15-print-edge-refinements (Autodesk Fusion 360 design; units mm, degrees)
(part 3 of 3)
extrude "Extrude2" cut sketch "E Rear Bearing Cap Bolt seed" profile of C1 along normal blind 3 (= "capThickness")
circular_pattern "C-Pattern1" TotalAngle 360
chamfer "Chamfer1" distance 0.3 (= "bedRelief")
work_plane "WorkPlane1" AlongDistance -29 (= "hubFace - adapterThickness") ExtraOffset 0
sketch "F Adapter Flange sketch" plane through (-20.5061, -20.5061, 0) normal (0.7071, 0.7071, 0) x axis (0, 0, 1)
  circle C1 centre (0, 0) radius 38
  dimension "d967" diameter C1 = 76 (= "mountOD")
extrude "Extrude1" new body sketch "F Adapter Flange sketch" along normal blind 6 (= "adapterThickness")
work_plane "WorkPlane2" AlongDistance -23 (= "hubFace") ExtraOffset 0
sketch "F Centering Pilot sketch" plane through (-16.2635, -16.2635, 0) normal (0.7071, 0.7071, 0) x axis (0, 0, 1)
  circle C1 centre (0, 0) radius 25
  circle C2 centre (0, 0) radius 17
  dimension "d972" diameter C1 = 50 (= "pilotDiameter")
  dimension "d973" diameter C2 = 34 (= "pilotInside")
extrude "Extrude2" add sketch "F Centering Pilot sketch" along normal blind 2 (= "pilotHeight")
work_plane "WorkPlane3" AlongDistance -29 (= "hubFace - adapterThickness") ExtraOffset 0
sketch "F Shaft Clearance sketch" plane through (-20.5061, -20.5061, 0) normal (0.7071, 0.7071, 0) x axis (0, 0, 1)
  circle C1 centre (0, 0) radius 4.25
  dimension "d978" diameter C1 = 8.5 (= "shaftClearance")
extrude "Extrude3" cut sketch "F Shaft Clearance sketch" along normal blind 6 (= "adapterThickness")
work_plane "WorkPlane4" AlongDistance -29 (= "hubFace - adapterThickness") ExtraOffset 0
sketch "F Mount Holes" plane through (-20.5061, -20.5061, 0) normal (0.7071, 0.7071, 0) x axis (0, 0, 1)
  circle C1 centre (22.6274, 22.6274) radius 2.15
  circle C2 centre (-22.6274, 22.6274) radius 2.15
  circle C3 centre (-22.6274, -22.6274) radius 2.15
  circle C4 centre (22.6274, -22.6274) radius 2.15
  point P1 (0, 0)
  point P2 (22.6274, 22.6274)
  point P3 (-22.6274, 22.6274)
  point P4 (-22.6274, -22.6274)
  point P5 (22.6274, -22.6274)
  dimension "d983" distance P1 P2 = 22.6274 (= "abs(mountCircle / ( 2 * sqrt(2) ))")
  dimension "d984" distance P1 P2 = 22.6274 (= "abs(mountCircle / ( 2 * sqrt(2) ))")
  dimension "d985" diameter C1 = 4.3 (= "m4Clearance")
  dimension "d986" distance P1 P3 = 22.6274 (= "abs(-mountCircle / ( 2 * sqrt(2) ))")
  dimension "d987" distance P1 P3 = 22.6274 (= "abs(mountCircle / ( 2 * sqrt(2) ))")
  dimension "d988" diameter C2 = 4.3 (= "m4Clearance")
  dimension "d989" distance P1 P4 = 22.6274 (= "abs(-mountCircle / ( 2 * sqrt(2) ))")
  dimension "d990" distance P1 P4 = 22.6274 (= "abs(-mountCircle / ( 2 * sqrt(2) ))")
  dimension "d991" diameter C3 = 4.3 (= "m4Clearance")
  dimension "d992" distance P1 P5 = 22.6274 (= "abs(mountCircle / ( 2 * sqrt(2) ))")
  dimension "d993" distance P1 P5 = 22.6274 (= "abs(-mountCircle / ( 2 * sqrt(2) ))")
  dimension "d994" diameter C4 = 4.3 (= "m4Clearance")
extrude "Extrude4" cut sketch "F Mount Holes" along normal blind 6 (= "adapterThickness")
sketch "F Compression Sleeve Holes" plane through (-20.5061, -20.5061, 0) normal (0.7071, 0.7071, 0) x axis (0, 0, 1)
  line L1 (11.3137, 0) -> (0, 0)
  line L2 (0, 11.3137) -> (0, 0)
  line L3 (-11.3137, 0) -> (0, 0)
  line L4 (0, -11.3137) -> (0, 0)
  circle C1 centre (11.3137, 0) radius 4.1
  circle C2 centre (0, 11.3137) radius 4.1
  circle C3 centre (-11.3137, 0) radius 4.1
  circle C4 centre (0, -11.3137) radius 4.1
  point P1 (0, 0)
  point P2 (11.3137, 0)
  point P3 (0, 11.3137)
  point P5 (0, -11.3137)
  horizontal L1
  vertical L2
  horizontal L3
  vertical L4
  dimension "d997" distance P1 P2 = 11.3137 (= "abs(hubHoleSpacing / sqrt(2))")
  dimension "d998" diameter C1 = 8.2 (= "sleeveOD + sleeveAllowance")
  dimension "d999" distance P1 P3 = 11.3137 (= "abs(hubHoleSpacing / sqrt(2))")
  dimension "d1000" diameter C2 = 8.2 (= "sleeveOD + sleeveAllowance")
  dimension "d59" = 150 (= "bodyWidth")
  dimension "d1002" diameter C3 = 8.2 (= "sleeveOD + sleeveAllowance")
  dimension "d1003" distance P1 P5 = 11.3137 (= "abs(-hubHoleSpacing / sqrt(2))")
  dimension "d1004" diameter C4 = 8.2 (= "sleeveOD + sleeveAllowance")
  dimension "d1001" distance = 11.3137 (= "abs(-hubHoleSpacing / sqrt(2))")
extrude "Extrude5" cut sketch "F Compression Sleeve Holes" profile of C1 C2 C3 C4 along normal blind 6 (= "adapterThickness")
chamfer "Chamfer1" distance 0.4 (= "entryChamfer")
chamfer "Chamfer2" distance 0.3 (= "bedRelief")
work_plane "WorkPlane1" AlongDistance 0.5 (= "qFront") ExtraOffset 0
sketch "Front 608 sketch" plane through (0.3536, 0.3536, 0) normal (0.7071, 0.7071, 0) x axis (0, 0, 1)
  circle C1 centre (0, 0) radius 11
  circle C2 centre (0, 0) radius 4
  dimension "d1011" diameter C1 = 22 (= "bearingOD")
  dimension "d1012" diameter C2 = 8 (= "bearingID")
extrude "Extrude1" new body sketch "Front 608 sketch" along normal blind 7 (= "bearingWidth")
work_plane "WorkPlane2" AlongDistance 25.6 (= "qRearBearing") ExtraOffset 0
sketch "Rear 608 sketch" plane through (18.1019, 18.1019, 0) normal (0.7071, 0.7071, 0) x axis (0, 0, 1)
  circle C1 centre (0, 0) radius 11
  circle C2 centre (0, 0) radius 4
  dimension "d1017" diameter C1 = 22 (= "bearingOD")
  dimension "d1018" diameter C2 = 8 (= "bearingID")
extrude "Extrude2" new body sketch "Rear 608 sketch" along normal blind 7 (= "bearingWidth")
work_plane "WorkPlane1" AlongDistance -24 ExtraOffset 0
sketch "Metal Shaft sketch" plane through (-16.9706, -16.9706, 0) normal (0.7071, 0.7071, 0) x axis (0, 0, 1)
  circle C1 centre (0, 0) radius 4
  dimension "d1023" diameter C1 = 8
extrude "Extrude1" new body sketch "Metal Shaft sketch" along normal blind 60
work_plane "WorkPlane1" AlongDistance -3.5 (= "qFront - 4 mm") ExtraOffset 0
sketch "Front Inner Ring Spacer sketch" plane through (-2.4749, -2.4749, 0) normal (0.7071, 0.7071, 0) x axis (0, 0, 1)
  circle C1 centre (0, 0) radius 5
  circle C2 centre (0, 0) radius 4
  dimension "d1028" diameter C1 = 10
  dimension "d1029" diameter C2 = 8
extrude "Extrude1" new body sketch "Front Inner Ring Spacer sketch" along normal blind 4
work_plane "WorkPlane2" AlongDistance 7.5 (= "qFront + bearingWidth") ExtraOffset 0
sketch "Rear Inner Ring Spacer sketch" plane through (5.3033, 5.3033, 0) normal (0.7071, 0.7071, 0) x axis (0, 0, 1)
  circle C1 centre (0, 0) radius 5
  circle C2 centre (0, 0) radius 4
  dimension "d1034" diameter C1 = 10
  dimension "d1035" diameter C2 = 8
extrude "Extrude2" new body sketch "Rear Inner Ring Spacer sketch" along normal blind 4
work_plane "WorkPlane1" AlongDistance -12.5 (= "qFront - 13 mm") ExtraOffset 0
sketch "Front Collar Maximum Envelope sketch" plane through (-8.8388, -8.8388, 0) normal (0.7071, 0.7071, 0) x axis (0, 0, 1)
  circle C1 centre (0, 0) radius 11.2
  circle C2 centre (0, 0) radius 4
  dimension "d1040" diameter C1 = 22.4
  dimension "d1041" diameter C2 = 8
extrude "Extrude1" new body sketch "Front Collar Maximum Envelope sketch" along normal blind 9
work_plane "WorkPlane2" AlongDistance 11.5 (= "qFront + bearingWidth + 4 mm") ExtraOffset 0
sketch "Rear Collar Maximum Envelope sketch" plane through (8.1317, 8.1317, 0) normal (0.7071, 0.7071, 0) x axis (0, 0, 1)
  circle C1 centre (0, 0) radius 11.2
  circle C2 centre (0, 0) radius 4
  dimension "d1046" diameter C1 = 22.4
  dimension "d1047" diameter C2 = 8
extrude "Extrude2" new body sketch "Rear Collar Maximum Envelope sketch" along normal blind 9
work_plane "WorkPlane1" AlongDistance 0 ExtraOffset 0
sketch "Spacer Pattern Axis" plane through (0, 0, 0) normal (0.7071, 0.7071, 0) x axis (0, 0, 1)
  circle C1 centre (0, 0) radius 0.5
  dimension "d1052" diameter C1 = 1
work_plane "WorkPlane2" AlongDistance 10.6 (= "qFrontBack") ExtraOffset 0
sketch "Support Spacer OD" plane through (7.4953, 7.4953, 0) normal (0.7071, 0.7071, 0) x axis (0, 0, 1)
  line L1 (17, 0) -> (0, 0)
  circle C1 centre (17, 0) radius 3
  circle C2 centre (17, 0) radius 1.6
  point P1 (0, 0)
  point P2 (17, 0)
  horizontal L1
  dimension "d1055" distance P1 P2 = 17 (= "supportCircle / 2")
  dimension "d1056" diameter C1 = 6 (= "supportSpacerOD")
  dimension "d1057" diameter C2 = 3.2
extrude "Extrude1" new body sketch "Support Spacer OD" profile of C1 C2 along normal blind 12 (= "supportSpacer")
circular_pattern "C-Pattern1" TotalAngle 360
work_plane "WorkPlane1" AlongDistance -29 (= "hubFace - adapterThickness") ExtraOffset 0
sketch "Sleeve 1 Outer" plane through (-20.5061, -20.5061, 0) normal (0.7071, 0.7071, 0) x axis (0, 0, 1)
  line L1 (11.3137, 0) -> (0, 0)
  circle C1 centre (11.3137, 0) radius 4
  circle C2 centre (11.3137, 0) radius 2.15
  point P1 (0, 0)
  point P2 (11.3137, 0)
  horizontal L1
  dimension "d1064" distance P1 P2 = 11.3137 (= "abs(hubHoleSpacing / sqrt(2))")
  dimension "d1065" diameter C1 = 8 (= "sleeveOD")
  dimension "d1066" diameter C2 = 4.3
extrude "Extrude1" new body sketch "Sleeve 1 Outer" profile of C1 C2 along normal blind 6 (= "adapterThickness")
work_plane "WorkPlane2" AlongDistance -29 (= "hubFace - adapterThickness") ExtraOffset 0
sketch "Sleeve 2 Outer" plane through (-20.5061, -20.5061, 0) normal (0.7071, 0.7071, 0) x axis (0, 0, 1)
  line L1 (0, 11.3137) -> (0, 0)
  circle C1 centre (0, 11.3137) radius 4
  circle C2 centre (0, 11.3137) radius 2.15
  point P1 (0, 0)
  point P2 (0, 11.3137)
  vertical L1
  dimension "d1071" distance P1 P2 = 11.3137 (= "abs(hubHoleSpacing / sqrt(2))")
  dimension "d1072" diameter C1 = 8 (= "sleeveOD")
  dimension "d1073" diameter C2 = 4.3
extrude "Extrude2" new body sketch "Sleeve 2 Outer" profile of C1 C2 along normal blind 6 (= "adapterThickness")
work_plane "WorkPlane3" AlongDistance -29 (= "hubFace - adapterThickness") ExtraOffset 0
sketch "Sleeve 3 Outer" plane through (-20.5061, -20.5061, 0) normal (0.7071, 0.7071, 0) x axis (0, 0, 1)
  line L1 (-11.3137, 0) -> (0, 0)
  circle C1 centre (-11.3137, 0) radius 4
  circle C2 centre (-11.3137, 0) radius 2.15
  point P1 (0, 0)
  point P2 (-11.3137, 0)
  horizontal L1
  dimension "d1078" distance P1 P2 = 11.3137 (= "abs(-hubHoleSpacing / sqrt(2))")
  dimension "d1079" diameter C1 = 8 (= "sleeveOD")
  dimension "d1080" diameter C2 = 4.3
extrude "Extrude3" new body sketch "Sleeve 3 Outer" profile of C1 C2 along normal blind 6 (= "adapterThickness")
work_plane "WorkPlane4" AlongDistance -29 (= "hubFace - adapterThickness") ExtraOffset 0
sketch "Sleeve 4 Outer" plane through (-20.5061, -20.5061, 0) normal (0.7071, 0.7071, 0) x axis (0, 0, 1)
  line L1 (0, -11.3137) -> (0, 0)
  circle C1 centre (0, -11.3137) radius 4
  circle C2 centre (0, -11.3137) radius 2.15
  point P1 (0, 0)
  point P2 (0, -11.3137)
  vertical L1
  dimension "d1085" distance P1 P2 = 11.3137 (= "abs(-hubHoleSpacing / sqrt(2))")
  dimension "d1086" diameter C1 = 8 (= "sleeveOD")
  dimension "d1087" diameter C2 = 4.3
extrude "Extrude4" new body sketch "Sleeve 4 Outer" profile of C1 C2 along normal blind 6 (= "adapterThickness")
work_plane "WorkPlane1" AlongDistance -23 (= "hubFace") ExtraOffset 0
sketch "Sonic Hub Body sketch" plane through (-16.2635, -16.2635, 0) normal (0.7071, 0.7071, 0) x axis (0, 0, 1)
  circle C1 centre (0, 0) radius 16
  circle C2 centre (0, 0) radius 4
  dimension "d1092" diameter C1 = 32
  dimension "d1093" diameter C2 = 8
extrude "Extrude1" new body sketch "Sonic Hub Body sketch" along normal blind 8
work_plane "WorkPlane2" AlongDistance -15 (= "hubFace + 8 mm") ExtraOffset 0
sketch "Sonic Hub Pilot sketch" plane through (-10.6066, -10.6066, 0) normal (0.7071, 0.7071, 0) x axis (0, 0, 1)
  circle C1 centre (0, 0) radius 7
  circle C2 centre (0, 0) radius 4
  dimension "d1098" diameter C1 = 14
  dimension "d1099" diameter C2 = 8
extrude "Extrude2" add sketch "Sonic Hub Pilot sketch" along normal blind 2
work_plane "WorkPlane3" AlongDistance -23 (= "hubFace") ExtraOffset 0
sketch "Hub M4 Thread Envelopes" plane through (-16.2635, -16.2635, 0) normal (0.7071, 0.7071, 0) x axis (0, 0, 1)
  line L1 (11.3137, 0) -> (0, 0)
  line L2 (0, 11.3137) -> (0, 0)
  line L3 (-11.3137, 0) -> (0, 0)
  line L4 (0, -11.3137) -> (0, 0)
  circle C1 centre (11.3137, 0) radius 2.15
  circle C2 centre (0, 11.3137) radius 2.15
  circle C3 centre (-11.3137, 0) radius 2.15
  circle C4 centre (0, -11.3137) radius 2.15
  point P1 (0, 0)
  point P2 (11.3137, 0)
  point P3 (0, 11.3137)
  point P5 (0, -11.3137)
  horizontal L1
  vertical L2
  horizontal L3
  vertical L4
  dimension "d1104" distance P1 P2 = 11.3137 (= "abs(hubHoleSpacing / sqrt(2))")
  dimension "d1105" diameter C1 = 4.3
  dimension "d1106" distance P1 P3 = 11.3137 (= "abs(hubHoleSpacing / sqrt(2))")
  dimension "d1107" diameter C2 = 4.3
  dimension "d59" = 150 (= "bodyWidth")
  dimension "d1109" diameter C3 = 4.3
  dimension "d1110" distance P1 P5 = 11.3137 (= "abs(-hubHoleSpacing / sqrt(2))")
  dimension "d1111" diameter C4 = 4.3
  dimension "d1108" distance = 11.3137 (= "abs(-hubHoleSpacing / sqrt(2))")
extrude "Extrude3" cut sketch "Hub M4 Thread Envelopes" profile of C1 C2 C3 C4 along normal blind 8
work_plane "WorkPlane1" AlongDistance -30 (= "hubFace - adapterThickness - 1 mm") ExtraOffset 0
sketch "Hub Screw 1 Profile" plane through (-21.2132, -21.2132, 0) normal (0.7071, 0.7071, 0) x axis (0, 0, 1)
  line L1 (11.3137, 0) -> (0, 0)
  circle C1 centre (11.3137, 0) radius 2
  point P1 (0, 0)
  point P2 (11.3137, 0)
  horizontal L1
  dimension "d1116" distance P1 P2 = 11.3137 (= "abs(hubHoleSpacing / sqrt(2))")
  dimension "d1117" diameter C1 = 4
extrude "Extrude1" new body sketch "Hub Screw 1 Profile" profile of C1 along normal blind 12
work_plane "WorkPlane2" AlongDistance -34 (= "hubFace - adapterThickness - 5 mm") ExtraOffset 0
sketch "Hub Screw Head 1 Profile" plane through (-24.0416, -24.0416, 0) normal (0.7071, 0.7071, 0) x axis (0, 0, 1)
  line L1 (11.3137, 0) -> (0, 0)
  circle C1 centre (11.3137, 0) radius 3.5
  point P1 (0, 0)
  point P2 (11.3137, 0)
  horizontal L1
  dimension "d1122" distance P1 P2 = 11.3137 (= "abs(hubHoleSpacing / sqrt(2))")
  dimension "d1123" diameter C1 = 7
extrude "Extrude2" new body sketch "Hub Screw Head 1 Profile" profile of C1 along normal blind 4
work_plane "WorkPlane3" AlongDistance -30 (= "hubFace - adapterThickness - 1 mm") ExtraOffset 0
sketch "Hub Washer 1 Outer" plane through (-21.2132, -21.2132, 0) normal (0.7071, 0.7071, 0) x axis (0, 0, 1)
  line L1 (11.3137, 0) -> (0, 0)
  circle C1 centre (11.3137, 0) radius 6
  circle C2 centre (11.3137, 0) radius 2.15
  point P1 (0, 0)
  point P2 (11.3137, 0)
  horizontal L1
  dimension "d1128" distance P1 P2 = 11.3137 (= "abs(hubHoleSpacing / sqrt(2))")
  dimension "d1129" diameter C1 = 12
  dimension "d1130" diameter C2 = 4.3
extrude "Extrude3" new body sketch "Hub Washer 1 Outer" profile of C1 C2 along normal blind 1
work_plane "WorkPlane4" AlongDistance -30 (= "hubFace - adapterThickness - 1 mm") ExtraOffset 0
sketch "Hub Screw 2 Profile" plane through (-21.2132, -21.2132, 0) normal (0.7071, 0.7071, 0) x axis (0, 0, 1)
  line L1 (0, 11.3137) -> (0, 0)
  circle C1 centre (0, 11.3137) radius 2
  point P1 (0, 0)
  point P2 (0, 11.3137)
  vertical L1
  dimension "d1135" distance P1 P2 = 11.3137 (= "abs(hubHoleSpacing / sqrt(2))")
  dimension "d1136" diameter C1 = 4
extrude "Extrude4" new body sketch "Hub Screw 2 Profile" profile of C1 along normal blind 12
work_plane "WorkPlane5" AlongDistance -34 (= "hubFace - adapterThickness - 5 mm") ExtraOffset 0
sketch "Hub Screw Head 2 Profile" plane through (-24.0416, -24.0416, 0) normal (0.7071, 0.7071, 0) x axis (0, 0, 1)
  line L1 (0, 11.3137) -> (0, 0)
  circle C1 centre (0, 11.3137) radius 3.5
  point P1 (0, 0)
  point P2 (0, 11.3137)
  vertical L1
  dimension "d1141" distance P1 P2 = 11.3137 (= "abs(hubHoleSpacing / sqrt(2))")
  dimension "d1142" diameter C1 = 7
extrude "Extrude5" new body sketch "Hub Screw Head 2 Profile" profile of C1 along normal blind 4
work_plane "WorkPlane6" AlongDistance -30 (= "hubFace - adapterThickness - 1 mm") ExtraOffset 0
sketch "Hub Washer 2 Outer" plane through (-21.2132, -21.2132, 0) normal (0.7071, 0.7071, 0) x axis (0, 0, 1)
  line L1 (0, 11.3137) -> (0, 0)
  circle C1 centre (0, 11.3137) radius 6
  circle C2 centre (0, 11.3137) radius 2.15
  point P1 (0, 0)
  point P2 (0, 11.3137)
  vertical L1
  dimension "d1147" distance P1 P2 = 11.3137 (= "abs(hubHoleSpacing / sqrt(2))")
  dimension "d1148" diameter C1 = 12
  dimension "d1149" diameter C2 = 4.3
extrude "Extrude6" new body sketch "Hub Washer 2 Outer" profile of C1 C2 along normal blind 1
work_plane "WorkPlane7" AlongDistance -30 (= "hubFace - adapterThickness - 1 mm") ExtraOffset 0
sketch "Hub Screw 3 Profile" plane through (-21.2132, -21.2132, 0) normal (0.7071, 0.7071, 0) x axis (0, 0, 1)
  line L1 (-11.3137, 0) -> (0, 0)
  circle C1 centre (-11.3137, 0) radius 2
  point P1 (0, 0)
  point P2 (-11.3137, 0)
  horizontal L1
  dimension "d1154" distance P1 P2 = 11.3137 (= "abs(-hubHoleSpacing / sqrt(2))")
  dimension "d1155" diameter C1 = 4
extrude "Extrude7" new body sketch "Hub Screw 3 Profile" profile of C1 along normal blind 12
work_plane "WorkPlane8" AlongDistance -34 (= "hubFace - adapterThickness - 5 mm") ExtraOffset 0
sketch "Hub Screw Head 3 Profile" plane through (-24.0416, -24.0416, 0) normal (0.7071, 0.7071, 0) x axis (0, 0, 1)
  line L1 (-11.3137, 0) -> (0, 0)
  circle C1 centre (-11.3137, 0) radius 3.5
  point P1 (0, 0)
  point P2 (-11.3137, 0)
  horizontal L1
  dimension "d1160" distance P1 P2 = 11.3137 (= "abs(-hubHoleSpacing / sqrt(2))")
  dimension "d1161" diameter C1 = 7
extrude "Extrude8" new body sketch "Hub Screw Head 3 Profile" profile of C1 along normal blind 4
work_plane "WorkPlane9" AlongDistance -30 (= "hubFace - adapterThickness - 1 mm") ExtraOffset 0
sketch "Hub Washer 3 Outer" plane through (-21.2132, -21.2132, 0) normal (0.7071, 0.7071, 0) x axis (0, 0, 1)
  line L1 (-11.3137, 0) -> (0, 0)
  circle C1 centre (-11.3137, 0) radius 6
  circle C2 centre (-11.3137, 0) radius 2.15
  point P1 (0, 0)
  point P2 (-11.3137, 0)
  horizontal L1
  dimension "d1166" distance P1 P2 = 11.3137 (= "abs(-hubHoleSpacing / sqrt(2))")
  dimension "d1167" diameter C1 = 12
  dimension "d1168" diameter C2 = 4.3
extrude "Extrude9" new body sketch "Hub Washer 3 Outer" profile of C1 C2 along normal blind 1
work_plane "WorkPlane10" AlongDistance -30 (= "hubFace - adapterThickness - 1 mm") ExtraOffset 0
sketch "Hub Screw 4 Profile" plane through (-21.2132, -21.2132, 0) normal (0.7071, 0.7071, 0) x axis (0, 0, 1)
  line L1 (0, -11.3137) -> (0, 0)
  circle C1 centre (0, -11.3137) radius 2
  point P1 (0, 0)
  point P2 (0, -11.3137)
  vertical L1
  dimension "d1173" distance P1 P2 = 11.3137 (= "abs(-hubHoleSpacing / sqrt(2))")
  dimension "d1174" diameter C1 = 4
extrude "Extrude10" new body sketch "Hub Screw 4 Profile" profile of C1 along normal blind 12
work_plane "WorkPlane11" AlongDistance -34 (= "hubFace - adapterThickness - 5 mm") ExtraOffset 0
sketch "Hub Screw Head 4 Profile" plane through (-24.0416, -24.0416, 0) normal (0.7071, 0.7071, 0) x axis (0, 0, 1)
  line L1 (0, -11.3137) -> (0, 0)
  circle C1 centre (0, -11.3137) radius 3.5
  point P1 (0, 0)
  point P2 (0, -11.3137)
  vertical L1
  dimension "d1179" distance P1 P2 = 11.3137 (= "abs(-hubHoleSpacing / sqrt(2))")
  dimension "d1180" diameter C1 = 7
extrude "Extrude11" new body sketch "Hub Screw Head 4 Profile" profile of C1 along normal blind 4
work_plane "WorkPlane12" AlongDistance -30 (= "hubFace - adapterThickness - 1 mm") ExtraOffset 0
sketch "Hub Washer 4 Outer" plane through (-21.2132, -21.2132, 0) normal (0.7071, 0.7071, 0) x axis (0, 0, 1)
  line L1 (0, -11.3137) -> (0, 0)
  circle C1 centre (0, -11.3137) radius 6
  circle C2 centre (0, -11.3137) radius 2.15
  point P1 (0, 0)
  point P2 (0, -11.3137)
  vertical L1
  dimension "d1185" distance P1 P2 = 11.3137 (= "abs(-hubHoleSpacing / sqrt(2))")
  dimension "d1186" diameter C1 = 12
  dimension "d1187" diameter C2 = 4.3
extrude "Extrude12" new body sketch "Hub Washer 4 Outer" profile of C1 C2 along normal blind 1
work_plane "WorkPlane1" AlongDistance -30 (= "hubFace - adapterThickness - 1 mm") ExtraOffset 0
sketch "Adapter Screw 1 Profile" plane through (-21.2132, -21.2132, 0) normal (0.7071, 0.7071, 0) x axis (0, 0, 1)
  circle C1 centre (22.6274, 22.6274) radius 2
  point P1 (0, 0)
  point P2 (22.6274, 22.6274)
  dimension "d1192" distance P1 P2 = 22.6274 (= "abs(mountCircle / ( 2 * sqrt(2) ))")
  dimension "d1193" distance P1 P2 = 22.6274 (= "abs(mountCircle / ( 2 * sqrt(2) ))")
  dimension "d1194" diameter C1 = 4
extrude "Extrude1" new body sketch "Adapter Screw 1 Profile" along normal blind 30
work_plane "WorkPlane2" AlongDistance -34 (= "hubFace - adapterThickness - 5 mm") ExtraOffset 0
sketch "Adapter Screw Head 1 Profile" plane through (-24.0416, -24.0416, 0) normal (0.7071, 0.7071, 0) x axis (0, 0, 1)
  circle C1 centre (22.6274, 22.6274) radius 3.5
  point P1 (0, 0)
  point P2 (22.6274, 22.6274)
  dimension "d1199" distance P1 P2 = 22.6274 (= "abs(mountCircle / ( 2 * sqrt(2) ))")
  dimension "d1200" distance P1 P2 = 22.6274 (= "abs(mountCircle / ( 2 * sqrt(2) ))")
  dimension "d1201" diameter C1 = 7
extrude "Extrude2" new body sketch "Adapter Screw Head 1 Profile" along normal blind 4
work_plane "WorkPlane3" AlongDistance -30 (= "hubFace - adapterThickness - 1 mm") ExtraOffset 0
sketch "Adapter Washer 1 Outer" plane through (-21.2132, -21.2132, 0) normal (0.7071, 0.7071, 0) x axis (0, 0, 1)
  circle C1 centre (22.6274, 22.6274) radius 4.5
  circle C2 centre (22.6274, 22.6274) radius 2.15
  point P1 (0, 0)
  point P2 (22.6274, 22.6274)
  dimension "d1206" distance P1 P2 = 22.6274 (= "abs(mountCircle / ( 2 * sqrt(2) ))")
  dimension "d1207" distance P1 P2 = 22.6274 (= "abs(mountCircle / ( 2 * sqrt(2) ))")
  dimension "d1208" diameter C1 = 9
  dimension "d1209" diameter C2 = 4.3
extrude "Extrude3" new body sketch "Adapter Washer 1 Outer" along normal blind 1
work_plane "WorkPlane4" ExtraOffset 0
sketch "Adapter Nut Hex 1" plane through (-3.182, -3.182, 0) normal (0.7071, 0.7071, 0) x axis (0, 0, 1)
  line L1 (24.6481, 26.1274) -> (26.6689, 22.6274)
  line L2 (20.6067, 26.1274) -> (24.6481, 26.1274)
  line L3 (18.586, 22.6274) -> (20.6067, 26.1274)
  line L4 (20.6067, 19.1274) -> (18.586, 22.6274)
  line L5 (24.6481, 19.1274) -> (20.6067, 19.1274)
  line L6 (26.6689, 22.6274) -> (24.6481, 19.1274)
  circle C1 centre (22.6274, 22.6274) radius 4.0415
  point P3 (26.6689, 22.6274)
  point P4 (24.6481, 26.1274)
  point P5 (20.6067, 26.1274)
  point P6 (18.586, 22.6274)
  point P7 (20.6067, 19.1274)
  point P8 (24.6481, 19.1274)
  point P1 (0, 0)
  point P2 (22.6274, 22.6274)
  coincident C1 P3
  coincident C1 P4
  coincident C1 P5
  coincident C1 P6
  coincident C1 P7
  coincident C1 P8
  equal L1 L2
  equal L1 L3
  equal L1 L4
  equal L1 L5
  equal L1 L6
  horizontal L2
  dimension "d1214" distance P1 P2 = 22.6274 (= "abs(mountCircle / ( 2 * sqrt(2) ))")
  dimension "d1215" distance P1 P2 = 22.6274 (= "abs(mountCircle / ( 2 * sqrt(2) ))")
  dimension "d1216" diameter C1 = 8.0829 (= "2 * ( 7 mm ) / sqrt(3)")
extrude "Extrude4" new body sketch "Adapter Nut Hex 1" profile of L1 L2 L3 L4 L5 L6 along normal blind 3.2
sketch "Nut Thread Clearance 1" plane through (-3.182, -3.182, 0) normal (0.7071, 0.7071, 0) x axis (0, 0, 1)
  circle C1 centre (22.6274, 22.6274) radius 2.15
  point P1 (0, 0)
  point P2 (22.6274, 22.6274)
  dimension "d1219" distance P1 P2 = 22.6274 (= "abs(mountCircle / ( 2 * sqrt(2) ))")
  dimension "d1220" distance P1 P2 = 22.6274 (= "abs(mountCircle / ( 2 * sqrt(2) ))")
  dimension "d1221" diameter C1 = 4.3
extrude "Extrude5" cut sketch "Nut Thread Clearance 1" along normal blind 3.2
work_plane "WorkPlane5" AlongDistance -30 (= "hubFace - adapterThickness - 1 mm") ExtraOffset 0
sketch "Adapter Screw 2 Profile" plane through (-21.2132, -21.2132, 0) normal (0.7071, 0.7071, 0) x axis (0, 0, 1)
  circle C1 centre (-22.6274, 22.6274) radius 2
  point P1 (0, 0)
  point P2 (-22.6274, 22.6274)
  dimension "d1226" distance P1 P2 = 22.6274 (= "abs(-mountCircle / ( 2 * sqrt(2) ))")
  dimension "d1227" distance P1 P2 = 22.6274 (= "abs(mountCircle / ( 2 * sqrt(2) ))")
  dimension "d1228" diameter C1 = 4
extrude "Extrude6" new body sketch "Adapter Screw 2 Profile" along normal blind 30
work_plane "WorkPlane6" AlongDistance -34 (= "hubFace - adapterThickness - 5 mm") ExtraOffset 0
sketch "Adapter Screw Head 2 Profile" plane through (-24.0416, -24.0416, 0) normal (0.7071, 0.7071, 0) x axis (0, 0, 1)
  circle C1 centre (-22.6274, 22.6274) radius 3.5
  point P1 (0, 0)
  point P2 (-22.6274, 22.6274)
  dimension "d1233" distance P1 P2 = 22.6274 (= "abs(-mountCircle / ( 2 * sqrt(2) ))")
  dimension "d1234" distance P1 P2 = 22.6274 (= "abs(mountCircle / ( 2 * sqrt(2) ))")
  dimension "d1235" diameter C1 = 7
extrude "Extrude7" new body sketch "Adapter Screw Head 2 Profile" along normal blind 4
work_plane "WorkPlane7" AlongDistance -30 (= "hubFace - adapterThickness - 1 mm") ExtraOffset 0
sketch "Adapter Washer 2 Outer" plane through (-21.2132, -21.2132, 0) normal (0.7071, 0.7071, 0) x axis (0, 0, 1)
  circle C1 centre (-22.6274, 22.6274) radius 4.5
  circle C2 centre (-22.6274, 22.6274) radius 2.15
  point P1 (0, 0)
  point P2 (-22.6274, 22.6274)
  dimension "d1240" distance P1 P2 = 22.6274 (= "abs(-mountCircle / ( 2 * sqrt(2) ))")
  dimension "d1241" distance P1 P2 = 22.6274 (= "abs(mountCircle / ( 2 * sqrt(2) ))")
  dimension "d1242" diameter C1 = 9
  dimension "d1243" diameter C2 = 4.3
extrude "Extrude8" new body sketch "Adapter Washer 2 Outer" along normal blind 1
work_plane "WorkPlane8" ExtraOffset 0
sketch "Adapter Nut Hex 2" plane through (-3.182, -3.182, 0) normal (0.7071, 0.7071, 0) x axis (0, 0, 1)
  line L1 (-20.6067, 26.1274) -> (-18.586, 22.6274)
  line L2 (-24.6481, 26.1274) -> (-20.6067, 26.1274)
  line L3 (-26.6689, 22.6274) -> (-24.6481, 26.1274)
  line L4 (-24.6481, 19.1274) -> (-26.6689, 22.6274)
  line L5 (-20.6067, 19.1274) -> (-24.6481, 19.1274)
  line L6 (-18.586, 22.6274) -> (-20.6067, 19.1274)
  circle C1 centre (-22.6274, 22.6274) radius 4.0415
  point P3 (-18.586, 22.6274)
  point P4 (-20.6067, 26.1274)
  point P5 (-24.6481, 26.1274)
  point P6 (-26.6689, 22.6274)
  point P7 (-24.6481, 19.1274)
  point P8 (-20.6067, 19.1274)
  point P1 (0, 0)
  point P2 (-22.6274, 22.6274)
  coincident C1 P3
  coincident C1 P4
  coincident C1 P5
  coincident C1 P6
  coincident C1 P7
  coincident C1 P8
  equal L1 L2
  equal L1 L3
  equal L1 L4
  equal L1 L5
  equal L1 L6
  horizontal L2
  dimension "d1248" distance P1 P2 = 22.6274 (= "abs(-mountCircle / ( 2 * sqrt(2) ))")
  dimension "d1249" distance P1 P2 = 22.6274 (= "abs(mountCircle / ( 2 * sqrt(2) ))")
  dimension "d1250" diameter C1 = 8.0829 (= "2 * ( 7 mm ) / sqrt(3)")
extrude "Extrude9" new body sketch "Adapter Nut Hex 2" profile of L1 L2 L3 L4 L5 L6 along normal blind 3.2
sketch "Nut Thread Clearance 2" plane through (-3.182, -3.182, 0) normal (0.7071, 0.7071, 0) x axis (0, 0, 1)
  circle C1 centre (-22.6274, 22.6274) radius 2.15
  point P1 (0, 0)
  point P2 (-22.6274, 22.6274)
  dimension "d1253" distance P1 P2 = 22.6274 (= "abs(-mountCircle / ( 2 * sqrt(2) ))")
  dimension "d1254" distance P1 P2 = 22.6274 (= "abs(mountCircle / ( 2 * sqrt(2) ))")
  dimension "d1255" diameter C1 = 4.3
extrude "Extrude10" cut sketch "Nut Thread Clearance 2" along normal blind 3.2
work_plane "WorkPlane9" AlongDistance -30 (= "hubFace - adapterThickness - 1 mm") ExtraOffset 0
sketch "Adapter Screw 3 Profile" plane through (-21.2132, -21.2132, 0) normal (0.7071, 0.7071, 0) x axis (0, 0, 1)
  circle C1 centre (-22.6274, -22.6274) radius 2
  point P1 (0, 0)
  point P2 (-22.6274, -22.6274)
  dimension "d1260" distance P1 P2 = 22.6274 (= "abs(-mountCircle / ( 2 * sqrt(2) ))")
  dimension "d1261" distance P1 P2 = 22.6274 (= "abs(-mountCircle / ( 2 * sqrt(2) ))")
  dimension "d1262" diameter C1 = 4
extrude "Extrude11" new body sketch "Adapter Screw 3 Profile" along normal blind 30
work_plane "WorkPlane10" AlongDistance -34 (= "hubFace - adapterThickness - 5 mm") ExtraOffset 0
sketch "Adapter Screw Head 3 Profile" plane through (-24.0416, -24.0416, 0) normal (0.7071, 0.7071, 0) x axis (0, 0, 1)
  circle C1 centre (-22.6274, -22.6274) radius 3.5
  point P1 (0, 0)
  point P2 (-22.6274, -22.6274)
  dimension "d1267" distance P1 P2 = 22.6274 (= "abs(-mountCircle / ( 2 * sqrt(2) ))")
  dimension "d1268" distance P1 P2 = 22.6274 (= "abs(-mountCircle / ( 2 * sqrt(2) ))")
  dimension "d1269" diameter C1 = 7
extrude "Extrude12" new body sketch "Adapter Screw Head 3 Profile" along normal blind 4
work_plane "WorkPlane11" AlongDistance -30 (= "hubFace - adapterThickness - 1 mm") ExtraOffset 0
sketch "Adapter Washer 3 Outer" plane through (-21.2132, -21.2132, 0) normal (0.7071, 0.7071, 0) x axis (0, 0, 1)
  circle C1 centre (-22.6274, -22.6274) radius 4.5
  circle C2 centre (-22.6274, -22.6274) radius 2.15
  point P1 (0, 0)
  point P2 (-22.6274, -22.6274)
  dimension "d1274" distance P1 P2 = 22.6274 (= "abs(-mountCircle / ( 2 * sqrt(2) ))")
  dimension "d1275" distance P1 P2 = 22.6274 (= "abs(-mountCircle / ( 2 * sqrt(2) ))")
  dimension "d1276" diameter C1 = 9
  dimension "d1277" diameter C2 = 4.3
extrude "Extrude13" new body sketch "Adapter Washer 3 Outer" along normal blind 1
work_plane "WorkPlane12" ExtraOffset 0
sketch "Adapter Nut Hex 3" plane through (-3.182, -3.182, 0) normal (0.7071, 0.7071, 0) x axis (0, 0, 1)
  line L1 (-20.6067, -19.1274) -> (-18.586, -22.6274)
  line L2 (-24.6481, -19.1274) -> (-20.6067, -19.1274)
  line L3 (-26.6689, -22.6274) -> (-24.6481, -19.1274)
  line L4 (-24.6481, -26.1274) -> (-26.6689, -22.6274)
  line L5 (-20.6067, -26.1274) -> (-24.6481, -26.1274)
  line L6 (-18.586, -22.6274) -> (-20.6067, -26.1274)
  circle C1 centre (-22.6274, -22.6274) radius 4.0415
  point P3 (-18.586, -22.6274)
  point P4 (-20.6067, -19.1274)
  point P5 (-24.6481, -19.1274)
  point P6 (-26.6689, -22.6274)
  point P7 (-24.6481, -26.1274)
  point P8 (-20.6067, -26.1274)
  point P1 (0, 0)
  point P2 (-22.6274, -22.6274)
  coincident C1 P3
  coincident C1 P4
  coincident C1 P5
  coincident C1 P6
  coincident C1 P7
  coincident C1 P8
  equal L1 L2
  equal L1 L3
  equal L1 L4
  equal L1 L5
  equal L1 L6
  horizontal L2
  dimension "d1282" distance P1 P2 = 22.6274 (= "abs(-mountCircle / ( 2 * sqrt(2) ))")
  dimension "d1283" distance P1 P2 = 22.6274 (= "abs(-mountCircle / ( 2 * sqrt(2) ))")
  dimension "d1284" diameter C1 = 8.0829 (= "2 * ( 7 mm ) / sqrt(3)")
extrude "Extrude14" new body sketch "Adapter Nut Hex 3" profile of L1 L2 L3 L4 L5 L6 along normal blind 3.2
sketch "Nut Thread Clearance 3" plane through (-3.182, -3.182, 0) normal (0.7071, 0.7071, 0) x axis (0, 0, 1)
  circle C1 centre (-22.6274, -22.6274) radius 2.15
  point P1 (0, 0)
  point P2 (-22.6274, -22.6274)
  dimension "d1287" distance P1 P2 = 22.6274 (= "abs(-mountCircle / ( 2 * sqrt(2) ))")
  dimension "d1288" distance P1 P2 = 22.6274 (= "abs(-mountCircle / ( 2 * sqrt(2) ))")
  dimension "d1289" diameter C1 = 4.3
extrude "Extrude15" cut sketch "Nut Thread Clearance 3" along normal blind 3.2
work_plane "WorkPlane13" AlongDistance -30 (= "hubFace - adapterThickness - 1 mm") ExtraOffset 0
sketch "Adapter Screw 4 Profile" plane through (-21.2132, -21.2132, 0) normal (0.7071, 0.7071, 0) x axis (0, 0, 1)
  circle C1 centre (22.6274, -22.6274) radius 2
  point P1 (0, 0)
  point P2 (22.6274, -22.6274)
  dimension "d1294" distance P1 P2 = 22.6274 (= "abs(mountCircle / ( 2 * sqrt(2) ))")
  dimension "d1295" distance P1 P2 = 22.6274 (= "abs(-mountCircle / ( 2 * sqrt(2) ))")
  dimension "d1296" diameter C1 = 4
extrude "Extrude16" new body sketch "Adapter Screw 4 Profile" along normal blind 30
work_plane "WorkPlane14" AlongDistance -34 (= "hubFace - adapterThickness - 5 mm") ExtraOffset 0
sketch "Adapter Screw Head 4 Profile" plane through (-24.0416, -24.0416, 0) normal (0.7071, 0.7071, 0) x axis (0, 0, 1)
  circle C1 centre (22.6274, -22.6274) radius 3.5
  point P1 (0, 0)
  point P2 (22.6274, -22.6274)
  dimension "d1301" distance P1 P2 = 22.6274 (= "abs(mountCircle / ( 2 * sqrt(2) ))")
  dimension "d1302" distance P1 P2 = 22.6274 (= "abs(-mountCircle / ( 2 * sqrt(2) ))")
  dimension "d1303" diameter C1 = 7
extrude "Extrude17" new body sketch "Adapter Screw Head 4 Profile" along normal blind 4
work_plane "WorkPlane15" AlongDistance -30 (= "hubFace - adapterThickness - 1 mm") ExtraOffset 0
sketch "Adapter Washer 4 Outer" plane through (-21.2132, -21.2132, 0) normal (0.7071, 0.7071, 0) x axis (0, 0, 1)
  circle C1 centre (22.6274, -22.6274) radius 4.5
  circle C2 centre (22.6274, -22.6274) radius 2.15
  point P1 (0, 0)
  point P2 (22.6274, -22.6274)
  dimension "d1308" distance P1 P2 = 22.6274 (= "abs(mountCircle / ( 2 * sqrt(2) ))")
  dimension "d1309" distance P1 P2 = 22.6274 (= "abs(-mountCircle / ( 2 * sqrt(2) ))")
  dimension "d1310" diameter C1 = 9
  dimension "d1311" diameter C2 = 4.3
extrude "Extrude18" new body sketch "Adapter Washer 4 Outer" along normal blind 1
work_plane "WorkPlane16" ExtraOffset 0
sketch "Adapter Nut Hex 4" plane through (-3.182, -3.182, 0) normal (0.7071, 0.7071, 0) x axis (0, 0, 1)
  line L1 (24.6481, -19.1274) -> (26.6689, -22.6274)
  line L2 (20.6067, -19.1274) -> (24.6481, -19.1274)
  line L3 (18.586, -22.6274) -> (20.6067, -19.1274)
  line L4 (20.6067, -26.1274) -> (18.586, -22.6274)
  line L5 (24.6481, -26.1274) -> (20.6067, -26.1274)
  line L6 (26.6689, -22.6274) -> (24.6481, -26.1274)
  circle C1 centre (22.6274, -22.6274) radius 4.0415
  point P3 (26.6689, -22.6274)
  point P4 (24.6481, -19.1274)
  point P5 (20.6067, -19.1274)
  point P6 (18.586, -22.6274)
  point P7 (20.6067, -26.1274)
  point P8 (24.6481, -26.1274)
  point P1 (0, 0)
  point P2 (22.6274, -22.6274)
  coincident C1 P3
  coincident C1 P4
  coincident C1 P5
  coincident C1 P6
  coincident C1 P7
  coincident C1 P8
  equal L1 L2
  equal L1 L3
  equal L1 L4
  equal L1 L5
  equal L1 L6
  horizontal L2
  dimension "d1316" distance P1 P2 = 22.6274 (= "abs(mountCircle / ( 2 * sqrt(2) ))")
  dimension "d1317" distance P1 P2 = 22.6274 (= "abs(-mountCircle / ( 2 * sqrt(2) ))")
  dimension "d1318" diameter C1 = 8.0829 (= "2 * ( 7 mm ) / sqrt(3)")
extrude "Extrude19" new body sketch "Adapter Nut Hex 4" profile of L1 L2 L3 L4 L5 L6 along normal blind 3.2
sketch "Nut Thread Clearance 4" plane through (-3.182, -3.182, 0) normal (0.7071, 0.7071, 0) x axis (0, 0, 1)
  circle C1 centre (22.6274, -22.6274) radius 2.15
  point P1 (0, 0)
  point P2 (22.6274, -22.6274)
  dimension "d1321" distance P1 P2 = 22.6274 (= "abs(mountCircle / ( 2 * sqrt(2) ))")
  dimension "d1322" distance P1 P2 = 22.6274 (= "abs(-mountCircle / ( 2 * sqrt(2) ))")
  dimension "d1323" diameter C1 = 4.3
extrude "Extrude20" cut sketch "Nut Thread Clearance 4" along normal blind 3.2
work_plane "WorkPlane1" AlongDistance 0 ExtraOffset 0
sketch "M3 Pattern Axis" plane through (0, 0, 0) normal (0.7071, 0.7071, 0) x axis (0, 0, 1)
  circle C1 centre (0, 0) radius 0.5
  dimension "d1328" diameter C1 = 1
work_plane "WorkPlane2" AlongDistance -8.7 (= "qRearEnd + capThickness + 0.5 mm - 45 mm") ExtraOffset 0
sketch "M3 Shank Profile" plane through (-6.1518, -6.1518, 0) normal (0.7071, 0.7071, 0) x axis (0, 0, 1)
  line L1 (17, 0) -> (0, 0)
  circle C1 centre (17, 0) radius 1.5
  point P1 (0, 0)
  point P2 (17, 0)
  horizontal L1
  dimension "d1331" distance P1 P2 = 17 (= "supportCircle / 2")
  dimension "d1332" diameter C1 = 3
extrude "Extrude1" new body sketch "M3 Shank Profile" profile of C1 along normal blind 45
work_plane "WorkPlane3" AlongDistance 36.3 (= "qRearEnd + capThickness + 0.5 mm") ExtraOffset 0
sketch "M3 Head Profile" plane through (25.668, 25.668, 0) normal (0.7071, 0.7071, 0) x axis (0, 0, 1)
  line L1 (17, 0) -> (0, 0)
  circle C1 centre (17, 0) radius 2.75
  point P1 (0, 0)
  point P2 (17, 0)
  horizontal L1
  dimension "d1337" distance P1 P2 = 17 (= "supportCircle / 2")
  dimension "d1338" diameter C1 = 5.5
extrude "Extrude2" new body sketch "M3 Head Profile" profile of C1 along normal blind 3
work_plane "WorkPlane4" AlongDistance 35.8 (= "qRearEnd + capThickness") ExtraOffset 0
sketch "Rear M3 Washer Profile" plane through (25.3144, 25.3144, 0) normal (0.7071, 0.7071, 0) x axis (0, 0, 1)
  line L1 (17, 0) -> (0, 0)
  circle C1 centre (17, 0) radius 3.5
  circle C2 centre (17, 0) radius 1.65
  point P1 (0, 0)
  point P2 (17, 0)
  horizontal L1
  dimension "d1343" distance P1 P2 = 17 (= "supportCircle / 2")
  dimension "d1344" diameter C1 = 7
  dimension "d1345" diameter C2 = 3.3
extrude "Extrude3" new body sketch "Rear M3 Washer Profile" profile of C1 C2 along normal blind 0.5
work_plane "WorkPlane5" AlongDistance -3 (= "qFront - capThickness - 0.5 mm") ExtraOffset 0
sketch "Front M3 Washer Profile" plane through (-2.1213, -2.1213, 0) normal (0.7071, 0.7071, 0) x axis (0, 0, 1)
  line L1 (17, 0) -> (0, 0)
  circle C1 centre (17, 0) radius 3.5
  circle C2 centre (17, 0) radius 1.65
  point P1 (0, 0)
  point P2 (17, 0)
  horizontal L1
  dimension "d1350" distance P1 P2 = 17 (= "supportCircle / 2")
  dimension "d1351" diameter C1 = 7
  dimension "d1352" diameter C2 = 3.3
extrude "Extrude4" new body sketch "Front M3 Washer Profile" profile of C1 C2 along normal blind 0.5
work_plane "WorkPlane6" AlongDistance -7 (= "qFront - capThickness - 4.5 mm") ExtraOffset 0
sketch "Front M3 Nyloc Envelope Profile" plane through (-4.9497, -4.9497, 0) normal (0.7071, 0.7071, 0) x axis (0, 0, 1)
  line L1 (17, 0) -> (0, 0)
  circle C1 centre (17, 0) radius 3.18
  circle C2 centre (17, 0) radius 1.65
  point P1 (0, 0)
  point P2 (17, 0)
  horizontal L1
  dimension "d1357" distance P1 P2 = 17 (= "supportCircle / 2")
  dimension "d1358" diameter C1 = 6.36
  dimension "d1359" diameter C2 = 3.3
extrude "Extrude5" new body sketch "Front M3 Nyloc Envelope Profile" profile of C1 C2 along normal blind 4
circular_pattern "C-Pattern1" TotalAngle 360
work_plane "WorkPlane25" RotateAngle 90 ExtraOffset 0
work_plane "WorkPlane26" AlongDistance 75 (= "bodyWidth / 2") ExtraOffset 0
work_plane "WorkPlane27" AlongDistance -35 ExtraOffset 0
ground "Pin"
as_built_joint "As-built1" RotateMinimum 0 RotateMaximum 180
as_built_joint "As-built2"
as_built_joint "As-built3"
as_built_joint "As-built4"
as_built_joint "As-built5"
as_built_joint "As-built6"
as_built_joint "As-built7"
as_built_joint "As-built8"
as_built_joint "As-built9"
as_built_joint "As-built10"
as_built_joint "As-built11"
as_built_joint "As-built12"
as_built_joint "As-built13"
as_built_joint "As-built14"
as_built_joint "As-built15"
work_plane "WorkPlane33" AlongDistance -35 ExtraOffset 0
sketch "PRINT-FIRST-A0-rim Crop Footprint" plane through (0, 0, -35) normal (0, 0, 1) x axis (1, 0, 0)
  line L1 (130, 66.5) -> (55, 66.5)
  line L2 (130, 75) -> (130, 66.5)
  line L3 (55, 75) -> (130, 75)
  line L4 (55, 66.5) -> (55, 75)
  point P1 (0, 0)
  point P2 (55, 66.5)
  point P3 (130, 66.5)
  point P4 (130, 75)
  point P5 (55, 75)
  dimension "d1451" distance P1 P2 = 55 (= "abs(55 mm)")
  dimension "d1452" distance P1 P2 = 66.5 (= "abs(66.5 mm)")
  dimension "d1453" distance P1 P3 = 130 (= "abs(130 mm)")
  dimension "d1454" distance P1 P3 = 66.5 (= "abs(66.5 mm)")
  dimension "d1455" distance P1 P4 = 130 (= "abs(130 mm)")
  dimension "d1456" distance P1 P4 = 75 (= "abs(75 mm)")
  dimension "d1457" distance P1 P5 = 55 (= "abs(55 mm)")
  dimension "d1458" distance P1 P5 = 75 (= "abs(75 mm)")
extrude "Extrude46" sketch "PRINT-FIRST-A0-rim Crop Footprint" along normal blind 70
work_plane "WorkPlane34" AlongDistance 90.1 ExtraOffset 0
sketch "PRINT-FIRST-A0-rim Level Bed Boundary" plane through (63.7103, 63.7103, 0) normal (0.7071, 0.7071, 0) x axis (0, 0, 1)
  line L1 (200, -200) -> (-200, -200)
  line L2 (200, 200) -> (200, -200)
  line L3 (-200, 200) -> (200, 200)
  line L4 (-200, -200) -> (-200, 200)
  line L5 (200, 200) -> (-200, -200)
  point P1 (0, 0)
  point P2 (-200, -200)
  point P3 (200, -200)
  point P4 (200, 200)
  horizontal L1
  vertical L2
  horizontal L3
  vertical L4
  midpoint P1 L5
  dimension "d1463" distance P2 P3 = 400
  dimension "d1464" distance P3 P4 = 400
extrude "Extrude47" sketch "PRINT-FIRST-A0-rim Level Bed Boundary" profile of L1 L2 L3 L4 along normal blind 300
work_plane "WorkPlane35" AlongDistance 66.5 ExtraOffset 0
sketch "PRINT-FIRST-A90-brace Crop Footprint" plane through (0, 0, 66.5) normal (0, 0, 1) x axis (1, 0, 0)
  line L1 (130, -35) -> (48, -35)
  line L2 (130, 35) -> (130, -35)
  line L3 (48, 35) -> (130, 35)
  line L4 (48, -35) -> (48, 35)
  point P1 (0, 0)
  point P2 (48, -35)
  point P3 (130, -35)
  point P4 (130, 35)
  point P5 (48, 35)
  dimension "d1469" distance P1 P2 = 48 (= "abs(48 mm)")
  dimension "d1470" distance P1 P2 = 35 (= "abs(-35 mm)")
  dimension "d1471" distance P1 P3 = 130 (= "abs(130 mm)")
  dimension "d1472" distance P1 P3 = 35 (= "abs(-35 mm)")
  dimension "d1473" distance P1 P4 = 130 (= "abs(130 mm)")
  dimension "d1474" distance P1 P4 = 35 (= "abs(35 mm)")
  dimension "d1475" distance P1 P5 = 48 (= "abs(48 mm)")
  dimension "d1476" distance P1 P5 = 35 (= "abs(35 mm)")
extrude "Extrude48" sketch "PRINT-FIRST-A90-brace Crop Footprint" along normal blind 8.5 bodies "A Housing print (1)"
work_plane "WorkPlane36" AlongDistance 50.1 ExtraOffset 0
sketch "PRINT-FIRST-A90-brace Level Bed Boundary" plane through (35.426, 35.426, 0) normal (0.7071, 0.7071, 0) x axis (0, 0, 1)
  line L1 (200, -200) -> (-200, -200)
  line L2 (200, 200) -> (200, -200)
  line L3 (-200, 200) -> (200, 200)
  line L4 (-200, -200) -> (-200, 200)
  line L5 (200, 200) -> (-200, -200)
  point P1 (0, 0)
  point P2 (-200, -200)
  point P3 (200, -200)
  point P4 (200, 200)
  horizontal L1
  vertical L2
  horizontal L3
  vertical L4
  midpoint P1 L5
  dimension "d1481" distance P2 P3 = 400
  dimension "d1482" distance P3 P4 = 400
extrude "Extrude49" sketch "PRINT-FIRST-A90-brace Level Bed Boundary" profile of L1 L2 L3 L4 along normal blind 300
remove_body "RemoveBody1"
work_plane "WorkPlane28" RotateAngle 90 ExtraOffset 0
work_plane "WorkPlane29" AlongDistance 75 (= "bodyWidth / 2") ExtraOffset 0
sketch "B Driver Pad 1 Slot" plane through (0, -75, 0) normal (0, -1, 0) x axis (-1, 0, 0)
  line L1 (36.5, 28.6274) -> (43, 28.6274)
  line L2 (43, 16.6274) -> (36.5, 16.6274)
  line L3 (36.5, 22.6274) -> (43, 22.6274)
  arc A1 centre (36.5, 22.6274) radius 6 clockwise from (36.5, 16.6274) to (36.5, 28.6274)
  arc A2 centre (43, 22.6274) radius 6 clockwise from (43, 28.6274) to (43, 16.6274)
  point P2 (43, 22.6274)
  point P7 (43, 22.6274)
  point P1 (0, 0)
  point P8 (36.5, 22.6274)
  coincident P2 P7
  tangent L1 A1
  tangent A1 L2
  tangent L2 A2
  tangent L1 A2
  parallel L1 L2
  horizontal L3
  dimension "d1489" distance P1 P2 = 43 (= "Linear Dimension-2")
  dimension "d1490" distance P1 P2 = 22.6274 (= "Linear Dimension-3")
  dimension "d1491" diameter A1 = 12
  dimension "d1492" distance P7 P8 = 6.5
extrude "Extrude49" add sketch "B Driver Pad 1 Slot" profile of L1 A1 L2 A2 no distance stored
sketch "B Driver Pad 2 Slot" plane through (0, -75, 0) normal (0, -1, 0) x axis (-1, 0, 0)
  line L1 (36.5, -16.6274) -> (43, -16.6274)
  line L2 (43, -28.6274) -> (36.5, -28.6274)
  line L3 (36.5, -22.6274) -> (43, -22.6274)
  arc A1 centre (36.5, -22.6274) radius 6 clockwise from (36.5, -28.6274) to (36.5, -16.6274)
  arc A2 centre (43, -22.6274) radius 6 clockwise from (43, -16.6274) to (43, -28.6274)
  point P2 (43, -22.6274)
  point P7 (43, -22.6274)
  point P1 (0, 0)
  point P8 (36.5, -22.6274)
  coincident P2 P7
  tangent L1 A1
  tangent A1 L2
  tangent L2 A2
  tangent L1 A2
  parallel L1 L2
  horizontal L3
  dimension "d1495" distance P1 P2 = 43 (= "Linear Dimension-2")
  dimension "d1496" distance P1 P2 = 22.6274 (= "Linear Dimension-3")
  dimension "d1497" diameter A1 = 12
  dimension "d1498" distance P7 P8 = 6.5
extrude "Extrude50" add sketch "B Driver Pad 2 Slot" profile of L1 A1 L2 A2 no distance stored
sketch "B Driver Pad 3 Slot" plane through (0, -75, 0) normal (0, -1, 0) x axis (-1, 0, 0)
  line L1 (100.5, -16.6274) -> (107, -16.6274)
  line L2 (107, -28.6274) -> (100.5, -28.6274)
  line L3 (100.5, -22.6274) -> (107, -22.6274)
  arc A1 centre (100.5, -22.6274) radius 6 clockwise from (100.5, -28.6274) to (100.5, -16.6274)
  arc A2 centre (107, -22.6274) radius 6 clockwise from (107, -16.6274) to (107, -28.6274)
  point P2 (107, -22.6274)
  point P7 (107, -22.6274)
  point P1 (0, 0)
  point P8 (100.5, -22.6274)
  coincident P2 P7
  tangent L1 A1
  tangent A1 L2
  tangent L2 A2
  tangent L1 A2
  parallel L1 L2
  horizontal L3
  dimension "d1501" distance P1 P2 = 107 (= "Linear Dimension-2")
  dimension "d1502" distance P1 P2 = 22.6274 (= "Linear Dimension-3")
  dimension "d1503" diameter A1 = 12
  dimension "d1504" distance P7 P8 = 6.5
extrude "Extrude51" add sketch "B Driver Pad 3 Slot" profile of L1 A1 L2 A2 no distance stored
sketch "B Driver Pad 4 Slot" plane through (0, -75, 0) normal (0, -1, 0) x axis (-1, 0, 0)
  line L1 (100.5, 28.6274) -> (107, 28.6274)
  line L2 (107, 16.6274) -> (100.5, 16.6274)
  line L3 (100.5, 22.6274) -> (107, 22.6274)
  arc A1 centre (100.5, 22.6274) radius 6 clockwise from (100.5, 16.6274) to (100.5, 28.6274)
  arc A2 centre (107, 22.6274) radius 6 clockwise from (107, 28.6274) to (107, 16.6274)
  point P2 (107, 22.6274)
  point P7 (107, 22.6274)
  point P1 (0, 0)
  point P8 (100.5, 22.6274)
  coincident P2 P7
  tangent L1 A1
  tangent A1 L2
  tangent L2 A2
  tangent L1 A2
  parallel L1 L2
  horizontal L3
  dimension "d1507" distance P1 P2 = 107 (= "Linear Dimension-2")
  dimension "d1508" distance P1 P2 = 22.6274 (= "Linear Dimension-3")
  dimension "d1509" diameter A1 = 12
  dimension "d1510" distance P7 P8 = 6.5
extrude "Extrude52" add sketch "B Driver Pad 4 Slot" profile of L1 A1 L2 A2 no distance stored
work_plane "WorkPlane30" AlongDistance -35 ExtraOffset 0
sketch "B Mount Driver Axes" plane through (-24.7487, -24.7487, 0) normal (0.7071, 0.7071, 0) x axis (0, 0, 1)
  circle C1 centre (22.6274, 22.6274) radius 2.5
  circle C2 centre (-22.6274, 22.6274) radius 2.5
  circle C3 centre (-22.6274, -22.6274) radius 2.5
  circle C4 centre (22.6274, -22.6274) radius 2.5
  point P1 (0, 0)
  point P2 (22.6274, 22.6274)
  point P3 (-22.6274, 22.6274)
  point P4 (-22.6274, -22.6274)
  point P5 (22.6274, -22.6274)
  dimension "d1515" distance P1 P2 = 22.6274 (= "abs(mountCircle / ( 2 * sqrt(2) ))")
  dimension "d1516" distance P1 P2 = 22.6274 (= "abs(mountCircle / ( 2 * sqrt(2) ))")
  dimension "d1517" diameter C1 = 5 (= "driverPort")
  dimension "d1518" distance P1 P3 = 22.6274 (= "abs(-mountCircle / ( 2 * sqrt(2) ))")
  dimension "d1519" distance P1 P3 = 22.6274 (= "abs(mountCircle / ( 2 * sqrt(2) ))")
  dimension "d1520" diameter C2 = 5 (= "driverPort")
  dimension "d1521" distance P1 P4 = 22.6274 (= "abs(-mountCircle / ( 2 * sqrt(2) ))")
  dimension "d1522" distance P1 P4 = 22.6274 (= "abs(-mountCircle / ( 2 * sqrt(2) ))")
  dimension "d1523" diameter C3 = 5 (= "driverPort")
  dimension "d1524" distance P1 P5 = 22.6274 (= "abs(mountCircle / ( 2 * sqrt(2) ))")
  dimension "d1525" distance P1 P5 = 22.6274 (= "abs(-mountCircle / ( 2 * sqrt(2) ))")
  dimension "d1526" diameter C4 = 5 (= "driverPort")
extrude "Extrude53" cut sketch "B Mount Driver Axes" no distance stored
chamfer "Chamfer7" distance 0.3 (= "bedRelief")
chamfer "Chamfer6" distance 0.3 (= "bedRelief")
chamfer "Chamfer7" sketch "A Facet 135 Triangle 1" distance 0.3 (= "printEntryRelief")
chamfer "Chamfer3" distance 0.3 (= "printEntryRelief")
chamfer "Chamfer4" distance 0.3 (= "printEntryRelief")
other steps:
base_feature "Base Feature1" bodies "A Housing print"
base_feature "Base Feature1" bodies "B Moving Body print"
create_component "CreateComponent1"
reparent_decal "ReparentDecal1"
remove_body "RemoveBody1"
create_component "CreateComponent2"
reparent_decal "ReparentDecal2"
remove_body "RemoveBody2"
create_component "CreateComponent3"
create_component "CreateComponent4"
create_component "CreateComponent5"
create_component "CreateComponent6"
create_component "CreateComponent7"
create_component "CreateComponent8"
create_component "CreateComponent9"
create_component "CreateComponent10"
create_component "CreateComponent11"
create_component "CreateComponent12"
create_component "CreateComponent13"
create_component "CreateComponent14"
create_component "CreateComponent15"
create_component "CreateComponent16"
named bodies: "A Housing print", "B Moving Body print", "A Housing print (1)"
